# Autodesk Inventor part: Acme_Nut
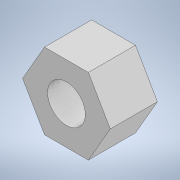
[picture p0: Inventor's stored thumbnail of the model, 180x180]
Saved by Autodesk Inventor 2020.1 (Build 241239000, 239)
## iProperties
Created: 2019-12
Part Number: Acme_Nut
Material: Generic
Document SubType Name: Modeling
Designer: Patrick Everitt
Density: 1 g/cm^3
Appearance: Default
Author: Patrick Everitt
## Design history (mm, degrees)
sketch "Sketch1"
  geometry: L1 (13.29, 23.019)-(26.58, 0); L2 (26.58, 0)-(13.29, -23.019); L3 (13.29, -23.019)-(-13.29, -23.019); L4 (-13.29, -23.019)-(-26.58, 0); L5 (-26.58, 0)-(-13.29, 23.019); L6 (-13.29, 23.019)-(13.29, 23.019); C1 r 11.43 at (0, 0); 2 further points
  constraints: 12 end point, 3 coincident, 1 centre point, 1 horizontal, 13 other
  dimensions: "d0" = 46.0375 distance between parallel lines of L3 L6; "d1" = 22.86 diameter of C1
extrude "Extrusion1" new body sketch "Sketch1" distance "d2" = 28.575; taper "d3" = 0 deg
body "Solid1"
